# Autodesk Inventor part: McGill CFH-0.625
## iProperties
Author: ARennick
Shininess: 64.0
Angle Display Precision: 2
Document Length Units: 11272
Document Angle Units: 11286
Document Time Units: 11279
Document Mass Units: 11290
Document Length Units Precision: 3
Document Angle Units Precision: 2
Compacted: True
PropertySet Name: _Private Model Information
Created: 2002-01
Part Number: McGill CFH-0.625
Description: Cam Follower - 0.625 Dia Slotted Open Straight Roller
Document SubType Name: Modeling
Designer: ARennick
Control State: 0
Master: False
Checked Out: False
PropertySet Name: Design Tracking Control
Density: 0.0
Volumn: 0.0
Area: 0.0
PropertySet Name: Model Information
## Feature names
1. Stud Body [Revolution]
2. Lube_Hole [Extrusion]
3. Slot [Extrusion]
4. Hex_Hole [Extrusion]
5. Oil_Hole [Hole]
6. Seals [Revolution]
7. Roller_Straight [Revolution]
8. Roller_Crowned [Revolution]
